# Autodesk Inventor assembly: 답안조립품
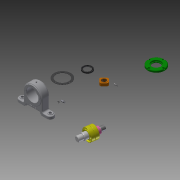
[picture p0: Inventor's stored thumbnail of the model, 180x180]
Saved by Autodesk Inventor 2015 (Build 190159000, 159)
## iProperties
Created: 2019-05
Part Number: 답안조립품
Document SubType Name: Assembly
Designer: now
Author: now
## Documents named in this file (13)
- C:\Users\now\Desktop\490504V1047\490504V1047\답안조립품.iam
- C:\Users\now\Desktop\490504V1047\490504V1047\개스킷.ipt
- C:\Users\now\Desktop\490504V1047\490504V1047\그리스니플 M6.ipt
- 그리스니플  M6.ipt
- C:\Users\now\Desktop\490504V1047\490504V1047\그리스니플개스킷.ipt
- C:\Users\now\Desktop\490504V1047\490504V1047\베어링너트.ipt
- C:\Users\now\Desktop\490504V1047\490504V1047\본체.ipt
- C:\Users\now\Desktop\490504V1047\490504V1047\볼트 M4.ipt
- C:\Users\now\Desktop\490504V1047\490504V1047\앵귤러 볼 베어링 7205.ipt
- C:\Users\now\Desktop\490504V1047\490504V1047\오일 실 28 40 5 B.ipt
- C:\Users\now\Desktop\490504V1047\490504V1047\축.ipt
- C:\Users\now\Desktop\490504V1047\490504V1047\칼라.ipt
- C:\Users\now\Desktop\490504V1047\490504V1047\커버.ipt
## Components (3 placed, 3 different names)
1. 개스킷:1
2. 그리스니플  M6:1
3. 그리스니플개스킷:1
